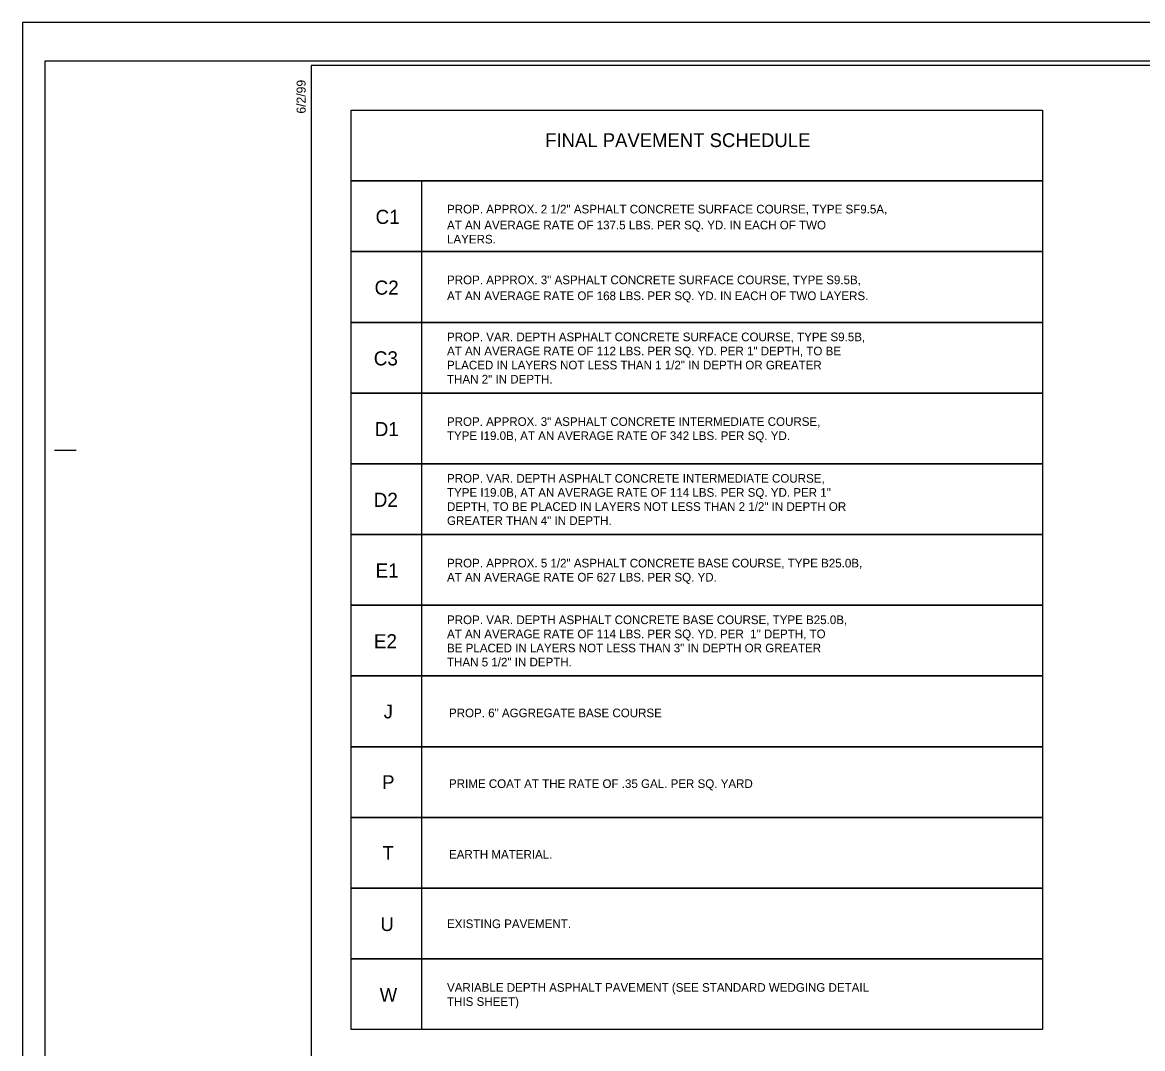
# Model space of a CAD drawing. Extents: x 1718167 to 1721223, y 797898 to 799800.
# Drawn here: x 1718866 to 1719514, y 798531 to 799124 of the extents above; entities that cross this region are included whole.
import ezdxf

# ---------------------------------------------------------------- set-up
doc = ezdxf.new("R2010")
doc.units = 0
for name, color, linetype in [('Prop Pavement Schedule Description CELL', 7, 'Continuous'), ('Sheet Cutting Line CELL', 7, 'Continuous'), ('Sheet Plot Border Inside CELL', 7, 'Continuous'), ('Sheet Plot Border Outside CELL', 7, 'Continuous'), ('Sheet Typical CELL', 7, 'Continuous')]:
    doc.layers.add(name, color=color, linetype=linetype)

msp = doc.modelspace()

# ---------------------------------------------------------------- linework, layer by layer
at = {"layer": 'Prop Pavement Schedule Description CELL'}
for p, q in [((1719056.13, 798828.15), (1719456.13, 798828.15)), ((1719456.13, 798828.15), (1719456.13, 798787.25)), ((1719097.04, 798787.25), (1719056.13, 798787.25)), ((1719456.13, 798787.25), (1719097.04, 798787.25)), ((1719097.04, 798623.6), (1719097.04, 798664.51))]:
    msp.add_line(p, q, dxfattribs=at)
msp.add_lwpolyline([(1719056.13, 799073.62), (1719456.14, 799073.62), (1719456.14, 799032.71), (1719056.13, 799032.71)], close=True, dxfattribs=at)
for points in [[(1719097.04, 798991.8), (1719056.13, 798991.8), (1719056.13, 799032.71), (1719456.13, 799032.71), (1719456.13, 798991.8), (1719097.04, 798991.8), (1719097.04, 799032.71)], [(1719097.04, 798950.88), (1719056.13, 798950.88), (1719056.13, 798991.8), (1719456.13, 798991.8), (1719456.13, 798950.88), (1719097.04, 798950.88), (1719097.04, 798991.8)], [(1719097.04, 798909.97), (1719056.13, 798909.97), (1719056.13, 798950.88), (1719456.14, 798950.88), (1719456.14, 798909.97), (1719097.04, 798909.97), (1719097.04, 798950.88)], [(1719097.04, 798869.06), (1719056.13, 798869.06), (1719056.13, 798909.97), (1719456.13, 798909.97), (1719456.13, 798869.06), (1719097.04, 798869.06), (1719097.04, 798909.97)], [(1719097.04, 798828.15), (1719056.13, 798828.15), (1719056.13, 798869.05), (1719456.14, 798869.05), (1719456.14, 798828.15), (1719097.04, 798828.15), (1719097.04, 798869.05)], [(1719097.04, 798787.24), (1719056.13, 798787.24), (1719056.13, 798828.15), (1719456.13, 798828.15), (1719456.13, 798787.24), (1719097.04, 798787.24), (1719097.04, 798828.15)], [(1719097.04, 798746.33), (1719056.13, 798746.33), (1719056.13, 798787.24), (1719456.13, 798787.24), (1719456.13, 798746.33), (1719097.04, 798746.33), (1719097.04, 798787.24)], [(1719097.04, 798705.42), (1719056.13, 798705.42), (1719056.13, 798746.33), (1719456.13, 798746.33), (1719456.13, 798705.42), (1719097.04, 798705.42), (1719097.04, 798746.33)], [(1719097.04, 798664.51), (1719056.13, 798664.51), (1719056.13, 798705.42), (1719456.13, 798705.42), (1719456.13, 798664.51), (1719097.04, 798664.51), (1719097.04, 798705.42)], [(1719097.04, 798623.6), (1719056.13, 798623.6), (1719056.13, 798664.51), (1719456.13, 798664.51), (1719456.13, 798623.6), (1719097.04, 798623.6), (1719097.04, 798664.51)], [(1719097.04, 798582.7), (1719056.13, 798582.7), (1719056.13, 798623.6), (1719456.14, 798623.6), (1719456.14, 798582.7), (1719097.04, 798582.7), (1719097.04, 798623.6)], [(1719097.04, 798541.79), (1719056.13, 798541.79), (1719056.13, 798582.7), (1719456.14, 798582.7), (1719456.14, 798541.79), (1719097.04, 798541.79), (1719097.04, 798582.7)]]:
    msp.add_lwpolyline(points, dxfattribs=at)
at = {"layer": 'Sheet Cutting Line CELL'}
for p, q in [((1720550, 799124.37), (1718866, 799124.37)), ((1718866, 799124.37), (1718866, 798024.37))]:
    msp.add_line(p, q, dxfattribs=at)
at = {"layer": 'Sheet Plot Border Inside CELL'}
msp.add_lwpolyline([(1720545.5, 799101.92), (1718879, 799101.92), (1718879, 798046.82), (1720545.5, 798046.82)], close=True, dxfattribs=at)
at = {"layer": 'Sheet Plot Border Outside CELL'}
msp.add_lwpolyline([(1720550, 799124.37), (1718866, 799124.37), (1718866, 798024.37), (1720550, 798024.37)], close=True, dxfattribs=at)
at = {"layer": 'Sheet Typical CELL'}
msp.add_line((1718884.5, 798876.87), (1718897, 798876.87), dxfattribs=at)
msp.add_lwpolyline([(1720533, 799099.37), (1719033, 799099.37), (1719033, 798049.37), (1720533, 798049.37)], close=True, dxfattribs=at)

# ---------------------------------------------------------------- texts
at = {"layer": 'Prop Pavement Schedule Description CELL'}
for s, height, p in [('FINAL PAVEMENT SCHEDULE', 8, (1719168.41, 799052.25)), ('PROP. APPROX. 2 1/2" ASPHALT CONCRETE SURFACE COURSE, TYPE SF9.5A,', 5, (1719111.62, 799013.86)), ('C1', 8.167, (1719070.27, 799007.8)), ('AT AN AVERAGE RATE OF 137.5 LBS. PER SQ. YD. IN EACH OF TWO ', 5, (1719111.62, 799004.65)), ('LAYERS.', 5, (1719111.62, 798996.49)), ('C2', 8.167, (1719069.7, 798966.88)), ('PROP. APPROX. 3" ASPHALT CONCRETE SURFACE COURSE, TYPE S9.5B,', 5, (1719111.62, 798972.94)), ('AT AN AVERAGE RATE OF 168 LBS. PER SQ. YD. IN EACH OF TWO LAYERS.', 5, (1719111.62, 798963.73)), ('PROP. VAR. DEPTH ASPHALT CONCRETE SURFACE COURSE, TYPE S9.5B,', 5, (1719111.62, 798939.96)), ('C3', 8.167, (1719069.24, 798925.96)), ('AT AN AVERAGE RATE OF 112 LBS. PER SQ. YD. PER 1" DEPTH, TO BE', 5, (1719111.62, 798931.8)), ('PLACED IN LAYERS NOT LESS THAN 1 1/2" IN DEPTH OR GREATER', 5, (1719111.62, 798923.65)), ('THAN 2" IN DEPTH.', 5, (1719111.62, 798915.49)), ('PROP. APPROX. 3" ASPHALT CONCRETE INTERMEDIATE COURSE,', 5, (1719111.58, 798890.97)), ('D1', 8.167, (1719069.77, 798885.06)), ('TYPE I19.0B, AT AN AVERAGE RATE OF 342 LBS. PER SQ. YD.', 5, (1719111.58, 798882.81)), ('PROP. VAR. DEPTH ASPHALT CONCRETE INTERMEDIATE COURSE,', 5, (1719111.62, 798858.14)), ('D2', 8.167, (1719069.2, 798844.15)), ('TYPE I19.0B, AT AN AVERAGE RATE OF 114 LBS. PER SQ. YD. PER 1" ', 5, (1719111.62, 798849.98)), ('DEPTH, TO BE PLACED IN LAYERS NOT LESS THAN 2 1/2" IN DEPTH OR', 5, (1719111.62, 798841.82)), ('GREATER THAN 4" IN DEPTH.', 5, (1719111.62, 798833.66)), ('E1', 8.167, (1719070.27, 798803.23)), ('PROP. APPROX. 5 1/2" ASPHALT CONCRETE BASE COURSE, TYPE B25.0B,', 5, (1719111.62, 798809.1)), ('AT AN AVERAGE RATE OF 627 LBS. PER SQ. YD.', 5, (1719111.62, 798800.95)), ('PROP. VAR. DEPTH ASPHALT CONCRETE BASE COURSE, TYPE B25.0B,', 5, (1719111.62, 798776.32)), ('AT AN AVERAGE RATE OF 114 LBS. PER SQ. YD. PER  1" DEPTH, TO', 5, (1719111.62, 798768.16)), ('E2', 8.167, (1719069.32, 798762.32)), ('BE PLACED IN LAYERS NOT LESS THAN 3" IN DEPTH OR GREATER', 5, (1719111.62, 798760)), ('THAN 5 1/2" IN DEPTH.', 5, (1719111.62, 798751.85)), ('J', 8, (1719074.96, 798721.8)), ('PROP. 6" AGGREGATE BASE COURSE', 5, (1719112.76, 798722.45)), ('P', 8, (1719074.11, 798680.89)), ('PRIME COAT AT THE RATE OF .35 GAL. PER SQ. YARD', 5, (1719112.76, 798681.54)), ('T', 8, (1719074.28, 798639.98)), ('EARTH MATERIAL.', 5, (1719112.76, 798640.63)), ('U', 8, (1719073.09, 798598.78)), ('EXISTING PAVEMENT.', 5, (1719111.62, 798600.48)), ('W', 8, (1719072.67, 798557.87)), ('VARIABLE DEPTH ASPHALT PAVEMENT (SEE STANDARD WEDGING DETAIL', 5, (1719111.62, 798563.65)), ('THIS SHEET)', 5, (1719111.62, 798555.5))]:
    msp.add_text(s, height=height, dxfattribs=at).set_placement(p)
at = {"layer": 'Sheet Typical CELL'}
msp.add_text('6/2/99', height=5.25, rotation=90, dxfattribs=at).set_placement((1719029.85, 799071.62))

doc.saveas('drawing.dxf')
